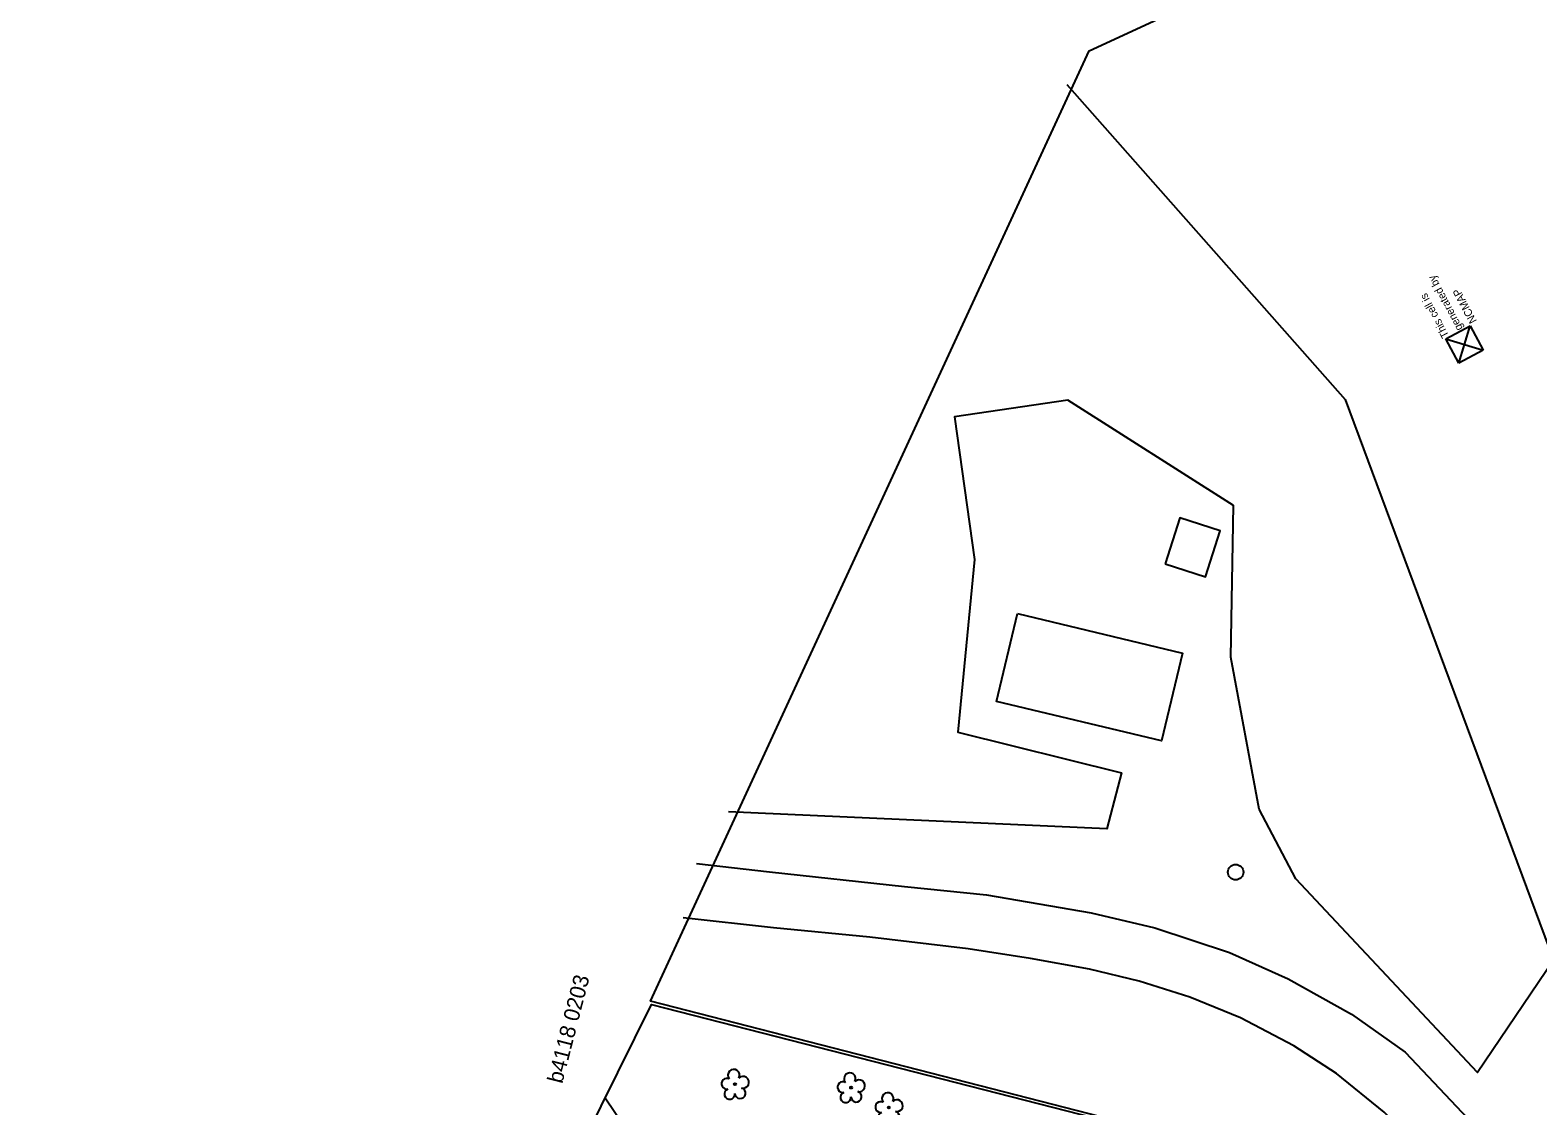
# Model space of a CAD drawing. Extents: x 1380524 to 1382335, y 594765 to 596944.
# Drawn here: x 1380768.5 to 1381250.1, y 596218 to 596561.6 of the extents above; entities that cross this region are included whole.
import ezdxf

# ---------------------------------------------------------------- set-up
doc = ezdxf.new("R2010")
doc.units = 0
for name, color, linetype in [('DTM Contours Major', 7, 'Continuous'), ('DTM Contours Major Text', 7, 'Continuous'), ('Prop Drainage Ditch Base Lines', 7, 'Continuous'), ('Prop Drainage Structure Box Number Symbol CELL', 7, 'Continuous'), ('Prop Drainage Structure Pipe CSP 15in', 7, 'Continuous'), ('Prop Drainage Structure Pipe Elbow CELL', 7, 'Continuous'), ('Prop Earthen Structure Cut Ditch Special Detail Label', 7, 'Continuous'), ('Prop Earthen Structure Ditch Flow Line', 7, 'Continuous'), ('Prop Erosion Rip Rap At Embankment Detail CELL', 7, 'Continuous')]:
    doc.layers.add(name, color=color, linetype=linetype)

# ---------------------------------------------------------------- blocks, each defined once
blk = doc.blocks.new('EXIST UTILITIES POWER TOWER')
at = {"layer": 'DTM Contours Major'}
for p, q in [((-0.0885, -0.0885), (-0.0885, 0.0885)), ((-0.0885, 0.0885), (0.0885, 0.0885)), ((0.0885, 0.0885), (-0.0885, -0.0885)), ((-0.0885, 0.0885), (0.0885, -0.0885)), ((0, 0), (0, 0)), ((0.0885, 0.0885), (0.0885, -0.0885)), ((0.0885, 0.0885), (0.0885, -0.0885)), ((0.0885, -0.0885), (-0.0885, -0.0885))]:
    blk.add_line(p, q, dxfattribs=at)
for s, p in [('This cell is', (0.0962, 0.0595)), ('generated by', (0.0962, -0.0405)), ('NCMAP', (0.0962, -0.1405))]:
    blk.add_text(s, height=0.05, dxfattribs=at).set_placement(p)
blk = doc.blocks.new('EXIST UTILITIES OTHER POLE')
at = {"layer": 'DTM Contours Major Text'}
blk.add_circle((0, 0), 0.0493, dxfattribs=at)
blk = doc.blocks.new('EXIST VEGETATION TREE')
at = {"layer": 'Prop Erosion Rip Rap At Embankment Detail CELL'}
blk.add_line((0, 0), (0, 0), dxfattribs=at)
blk.add_circle((0, 0), 0.00652, dxfattribs=at)
for centre, radius, start, end in [((-0.0521, 0.0031), 0.0345, 62.66361, 279.3457), ((-0.0077, 0.0575), 0.0371, 330.16508, 219.71335), ((0.051, 0.0118), 0.038, 257.1011, 134.19993), ((-0.0341, -0.0624), 0.0338, 111.56708, 6.23104), ((0.0335, -0.058), 0.034, 181.28216, 74.55999)]:
    blk.add_arc(centre, radius, start, end, dxfattribs=at)

msp = doc.modelspace()

# ---------------------------------------------------------------- linework, layer by layer
at = {"layer": 'Prop Drainage Ditch Base Lines'}
for points in [[(1381131.02, 596391.1), (1381143.9, 596386.96), (1381148.62, 596401.66), (1381135.74, 596405.8)], [(1381083.83, 596375.25), (1381136.58, 596362.65), (1381129.88, 596334.56), (1381077.12, 596347.15)]]:
    msp.add_lwpolyline(points, close=True, dxfattribs=at)
at = {"layer": 'Prop Drainage Structure Box Number Symbol CELL'}
for points in [[(1382083.99, 595964.39), (1380966.64, 596251.47), (1381106.82, 596554.99), (1381897.61, 596920.15), (1382148.43, 596473.2)], [(1382083.62, 595964.41), (1382120.69, 595773.82), (1382095.82, 595646.75), (1382010.85, 595488.75), (1381848.52, 595352.32), (1381617.36, 595239.15), (1381304.92, 595184.07), (1381005.77, 595330.75), (1380937.13, 595525.19), (1380768.47, 595849.39), (1380967, 596250.36)]]:
    msp.add_lwpolyline(points, close=True, dxfattribs=at)
at = {"layer": 'Prop Drainage Structure Pipe Elbow CELL'}
msp.add_lwpolyline([(1380952.13, 596220.51), (1380970.03, 596193.99), (1380974.48, 596180.61), (1380969.19, 596159.57)], dxfattribs=at)
at = {"layer": 'Prop Earthen Structure Cut Ditch Special Detail Label'}
msp.add_lwpolyline([(1381099.67, 596544.32), (1381188.54, 596443.63), (1381255.07, 596264.49), (1381230.85, 596228.68), (1381172.77, 596290.45), (1381161.09, 596312.72), (1381151.97, 596361.33), (1381152.87, 596409.75), (1381100, 596443.47), (1381063.73, 596438.1), (1381070.19, 596392.54), (1381064.84, 596337.41), (1381117.05, 596324.33), (1381112.45, 596306.47), (1380991.53, 596311.89)], dxfattribs=at)
at = {"layer": 'Prop Earthen Structure Ditch Flow Line'}
for points in [[(1380981.36, 596295.45), (1381004.67, 596292.69), (1381047.81, 596288.08), (1381074, 596285.4), (1381107.37, 596279.68), (1381127.78, 596274.86), (1381151.56, 596266.92), (1381170.38, 596258.53), (1381190.52, 596247.28), (1381207.69, 596235.17), (1381231.31, 596210.09), (1381240.31, 596197.1), (1381246.12, 596186.92)], [(1381221.65, 596191.89), (1381211.91, 596204.63), (1381200.96, 596215.94), (1381185.79, 596228.36), (1381172.19, 596237.19), (1381155.12, 596246.05), (1381138.89, 596252.74), (1381122.76, 596257.84), (1381106.86, 596261.65), (1381088.06, 596265.04), (1381068.1, 596268.1), (1381036.65, 596271.91), (1381005.93, 596274.84), (1380977.07, 596278.02)]]:
    msp.add_lwpolyline(points, dxfattribs=at)

# ---------------------------------------------------------------- block references
at = {"layer": 'DTM Contours Major', "xscale": 50, "yscale": 50, "rotation": 117.93083611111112}
msp.add_blockref('EXIST UTILITIES POWER TOWER', (1381226.69, 596461.2), dxfattribs=at)
at = {"layer": 'DTM Contours Major Text', "xscale": 50, "yscale": 50}
msp.add_blockref('EXIST UTILITIES OTHER POLE', (1381153.56, 596292.64), dxfattribs=at)
at = {"layer": 'Prop Erosion Rip Rap At Embankment Detail CELL', "xscale": 50, "yscale": 50}
for p in [(1380993.63, 596224.9), (1381030.7, 596223.79), (1381042.8, 596217.44)]:
    msp.add_blockref('EXIST VEGETATION TREE', p, dxfattribs=at)

# ---------------------------------------------------------------- texts
at = {"layer": 'Prop Drainage Structure Pipe CSP 15in'}
msp.add_text('b4118 0203', height=5, rotation=75.6415, dxfattribs=at).set_placement((1380938.44, 596224.85))

doc.saveas('drawing.dxf')
